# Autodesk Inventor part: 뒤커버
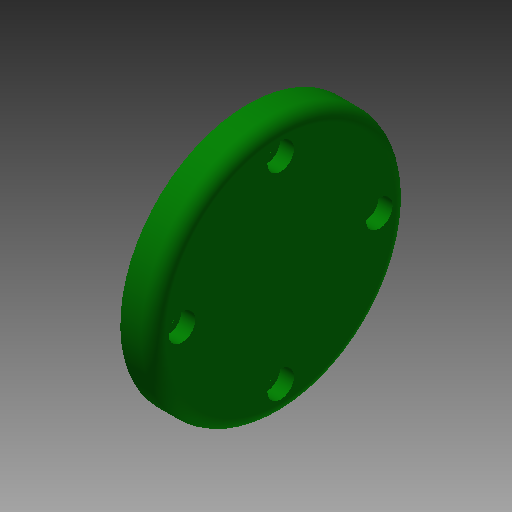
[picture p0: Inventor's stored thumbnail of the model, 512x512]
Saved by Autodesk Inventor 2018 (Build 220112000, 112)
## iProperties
Created: 2015-09
Part Number: 뒤커버
Material: 알루미늄 6061
Document SubType Name: Modeling
Designer: mduedu
Density: 2.71 g/cm^3
Mass: 54.0417 g
Surface Area: 84.9688 cm^2
Volume: 19.9416 cm^3
Appearance: 진녹색
Author: mduedu
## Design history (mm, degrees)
sketch "스케치1"
  geometry: L1 (-15.5, 47)-(-15.5, 78); L2 (-15.5, 78)-(-23.5, 78); L3 (-23.5, 78)-(-23.5, 67); L4 (-27.5, 67)-(-27.5, 47); L5 (-79.5, 39.5)-(-79.5, 54.5) reference; L6 (48.5, 54.5)-(48.5, 39.5) reference; L7 (-79.5, 47)-(48.5, 47); L8 (-23.5, 67)-(-27.5, 67); L9 (-27.5, 47)-(-15.5, 47); 1 further point
  constraints: 14 end point, 4 midpoint, 3 parallel, 1 collinear, 1 point on line, 1 vertical
  dimensions: "d6" = 62 diameter of L2 L7; "d7" = 8 distance of L1.end L2.end; "d8" = 40 diameter of L3.end L7; "d32" = 12 distance between parallel lines of L1 L4
revolve "회전1" sketch "스케치1" stored, may be unused: angle "d4" = 90 deg
sketch "스케치4"
  geometry: C1 r 31 at (0, 0) reference; 2 further points
  constraints: 1 coincident
hole "구멍3" sketch "스케치4" at (0, 0) diameter "d33" = 33; stored, may be unused: countersink angle "d37" = 90 deg, drill point angle "d39" = 0 deg; dims "d34" = 6, "d35" = 4, "d36" = 2, "d38" = 5
fillet "모깎기4" dims "d56" = 3
chamfer "모따기2" distance "d41" = 1; stored, may be unused: second distance "d42" = 2, angle "d43" = 45 deg
sketch "스케치5" dims "d44" = 48
  geometry: C1 r 31 at (0, 0) reference; 6 further points
  constraints: 2 vertical alignment, 1 coincident, 7 other
  dimensions: "d47" = 360 deg dimension on C1.centre point (0, -24) (derived)
sketch "스케치6"
  geometry: C1 r 28 at (0, 0) reference; A1 r 24 centre (0, 0) between (24, 0) and (0, 24); 2 further points
  constraints: 4 point on circle, 2 horizontal alignment, 2 vertical alignment, 1 centre point, 1 coincident
  dimensions: "d57" = 48 diameter of A1
hole "구멍4" sketch "스케치6" at (24, 0), (0, 24), (-24, 0), (0, -24) diameter "d49" = 3.4; stored, may be unused: countersink angle "d53" = 90 deg, drill point angle "d55" = 0 deg; dims "d50" = 6, "d51" = 6.5, "d52" = 3.4, "d54" = 8
node "솔리드1"
node "참조1"
node "참조2"
